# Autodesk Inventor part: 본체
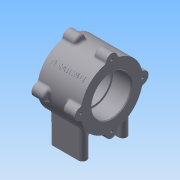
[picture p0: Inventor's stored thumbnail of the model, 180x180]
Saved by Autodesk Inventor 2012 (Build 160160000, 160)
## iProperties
Created: 2015-03
Part Number: 본체
Material: 알루미늄-6061
Document SubType Name: Modeling
Designer: net
Density: 2.71 g/cm^3
Mass: 454.88 g
Surface Area: 336.357 cm^2
Volume: 167.852 cm^3
Author: net
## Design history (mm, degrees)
sketch "스케치1"
  geometry: C1 r 37 at (0, 0); 1 further point
  constraints: 1 centre point, 1 coincident
  dimensions: "d0" = 74 diameter of C1
extrude "돌출1" new body sketch "스케치1" stored distance "d1" = 52; taper "d2" = 0 deg
sketch "스케치2"
  geometry: C1 r 7 at (0, 37); C2 r 7 at (-37, 0); C3 r 7 at (0, -37); C4 r 7 at (37, 0); A1 r 37 centre (0, 0) between (0, 37) and (-37, 0) reference
  constraints: 4 centre point, 4 point on circle, 2 horizontal alignment, 2 vertical alignment
  dimensions: "d3" = 14 diameter of C1; "d4" = 14 diameter of C2; "d5" = 14 diameter of C3; "d6" = 14 diameter of C4
extrude "돌출2" join sketch "스케치2" distance "d7" = 15; taper "d8" = 0 deg
sketch "스케치3"
  geometry: C1 r 7 at (0, 37); C2 r 7 at (37, 0); C3 r 7 at (0, -37); C4 r 7 at (-37, 0); A1 r 37 centre (0, 0) between (0, 37) and (37, 0) reference
  constraints: 4 centre point, 4 point on circle, 2 horizontal alignment, 2 vertical alignment
  dimensions: "d9" = 14 diameter of C1; "d10" = 14 diameter of C2; "d11" = 14 diameter of C3; "d12" = 14 diameter of C4
extrude "돌출3" join sketch "스케치3" distance "d13" = 15; taper "d14" = 0 deg
node "작업 평면1"
sketch "스케치4"
  geometry: L1 (0, 0)-(0, -58); L2 (0, -58)-(-24, -58); L3 (-24, -58)-(-29, -58); L4 (-29, -58)-(-19, -58); L5 (-19, -58)-(-19, -31.749); L6 (-29, -58)-(-29, -22.978); L7 (19, -58)-(19, -31.749); L8 (29, -58)-(29, -22.978); L9 (0, -58)-(24, -58); L10 (24, -58)-(29, -58); A1 r 37 centre (0, 0) between (-29, -22.978) and (-19, -31.749) reference; A2 r 37 centre (0, 0) between (19, -31.749) and (29, -22.978); A3 r 37 centre (0, 0) between (-29, -22.978) and (-19, -31.749); 1 further point
  constraints: 20 end point, 6 point on circle, 5 symmetric about line, 2 centre point, 2 perpendicular, 2 point on line, 1 coincident, 1 collinear, 1 parallel, 1 vertical
  dimensions: "d15" = 58 distance of L1.start L1.end; "d16" = 24 distance of L1.end L2.end; "d17" = 5 distance of L2.end L3.end; "d18" = 10 distance of L3.end L4.end
extrude "돌출4" join sketch "스케치4" stored distance "d20" = 40; taper "d21" = 0 deg
sketch "스케치5"
  geometry: C1 r 23.5 at (0, 0); A1 r 37 centre (0, 0) between (-6.969, 36.338) and (-36.338, 6.969) reference
  constraints: 1 centre point, 1 coincident
  dimensions: "d22" = 47 diameter of C1
extrude "돌출5" cut sketch "스케치5" distance "d23" = 22; taper "d24" = 0 deg
sketch "스케치6"
  geometry: C1 r 23.5 at (0, 0); A1 r 37 centre (0, 0) between (36.338, 6.969) and (6.969, 36.338) reference
  constraints: 1 centre point, 1 coincident
  dimensions: "d25" = 47 diameter of C1
extrude "돌출6" cut sketch "스케치6" distance "d26" = 22; taper "d27" = 0 deg
sketch "스케치7"
  geometry: C1 r 23.5 at (0, 0) reference; C2 r 21 at (0, 0)
  constraints: 1 centre point, 1 coincident
  dimensions: "d28" = 42 diameter of C2
extrude "돌출7" cut sketch "스케치7" distance "d29" = 22; taper "d30" = 0 deg
sketch "스케치8"
  geometry: A1 r 7 centre (0, 37) between (6.969, 36.338) and (-6.969, 36.338) reference; 1 further point
  constraints: 1 coincident
hole "구멍1" sketch "스케치8" at (0, 37) diameter "d31" = 3.242; stored, may be unused: countersink angle "d35" = 90 deg, drill point angle "d37" = 118 deg; dims "d32" = 8, "d33" = 4, "d34" = 2, "d36" = 11
sketch "스케치9"
  geometry: A1 r 7 centre (0, 37) between (6.969, 36.338) and (-6.969, 36.338) reference; 1 further point
  constraints: 1 coincident
hole "구멍2" sketch "스케치9" at (0, 37) diameter "d41" = 3.242; stored, may be unused: countersink angle "d45" = 90 deg, drill point angle "d47" = 118 deg; dims "d42" = 8, "d43" = 4, "d44" = 2, "d46" = 11
sketch "스케치10"
  geometry: L1 (0, 0)-(0, -40) reference; L2 (0, -40)-(10, -40) reference; L3 (-38, 0)-(-48, 0) reference; L4 (-48, -40)-(-48, 0) reference; L5 (-48, -40)-(-38, -40) reference; L6 (-38, 0)-(-38, -40) reference; L7 (5, -40)-(-43, -40); L8 (-43, -40)-(-43, -35); L9 (5, -40)-(5, -35); L10 (0, -20)-(-19, -20); 4 further points
  constraints: 8 end point, 3 midpoint, 2 coincident, 2 perpendicular, 2 symmetric about line, 1 parallel
  dimensions: "d51" = 48 distance of L7.start L7.end; "d52" = 5 distance of L7.end L8.end; "d53" = 5 distance of L7.start L9.end
hole "구멍3" sketch "스케치10" at (-43, -35), (5, -35), (-43, -5), (5, -5) diameter "d54" = 4.134; stored, may be unused: countersink angle "d58" = 90 deg, drill point angle "d60" = 118 deg; dims "d55" = 6, "d56" = 4, "d57" = 2, "d59" = 8
fillet "모깎기1" dims "d61" = 3
chamfer "모따기1" distance "d62" = 1; stored, may be unused: second distance "d63" = 2, angle "d64" = 45 deg
fillet "모깎기2" dims "d65" = 0.3
fillet "모깎기3" dims "d66" = 5
fillet "모깎기4" dims "d67" = 3
sketch "스케치11"
  geometry: L1 (-19, -36.661)-(-19, -58) reference; L2 (-19, -58)-(-29, -58) reference; L3 (-29, -58)-(-29, -24) reference; L4 (29, -24)-(29, -58) reference; L5 (29, -58)-(19, -58) reference; L6 (19, -58)-(19, -36.661) reference; L7 (0, 0)-(0, 12.332); L8 (0, 0)-(-26.163, 26.163); C1 r 21 at (0, 0) reference; A1 r 3 centre (16, -36.661) between (19, -36.661) and (14.8, -33.911) reference; A2 r 37 centre (0, 0) between (-14.8, -33.911) and (14.8, -33.911) reference; A3 r 3 centre (-16, -36.661) between (-14.8, -33.911) and (-19, -36.661) reference; A4 r 3 centre (-32, -24) between (-29, -24) and (-29.6, -22.2) reference; A5 r 37 centre (0, 0) between (29.6, -22.2) and (-29.6, -22.2) reference; A6 r 3 centre (32, -24) between (29.6, -22.2) and (29, -24) reference; 1 further point
  constraints: 4 end point, 1 parallel, 1 point on circle
  dimensions: "d68" = 45 deg angle of L8 L7
  node "절단 모서리 투영2"
node "작업 평면2"
sketch "스케치12"
  geometry: 2 further points
  constraints: 1 coincident, 1 other
feature "엠보싱1" sketch "스케치12" dims "d1" = 52, "d2" = 0, "d12" = 14, "d69" = 0.5, "d70" = 0
node "솔리드1"
pattern_circular "원형 패턴1" dims angle "d39" = 360 deg
pattern_circular "원형 패턴2" dims angle "d49" = 360 deg
node "투영된 루프1"
node "절단 모서리 투영1"
